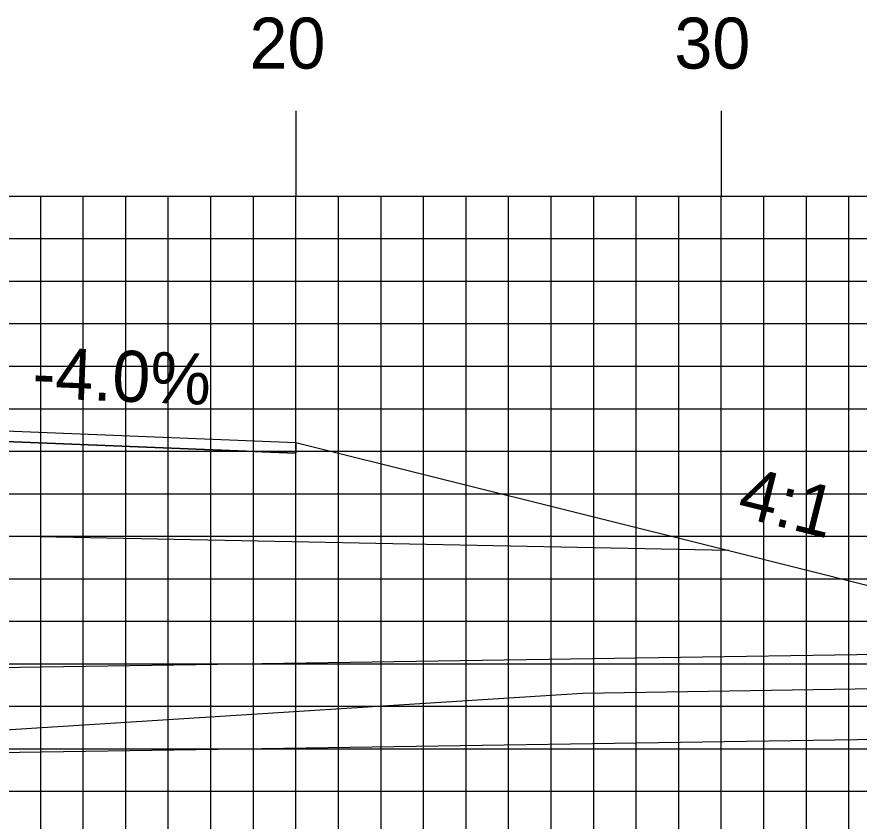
# Model space of a CAD drawing. Extents: x 1777531 to 1777875, y 442591 to 442811.
# Drawn here: x 1777710.72 to 1777730.52, y 442618.96 to 442637.88 of the extents above; entities that cross this region are included whole.
import ezdxf

# ---------------------------------------------------------------- set-up
doc = ezdxf.new("R2010")
doc.units = 0
for name, color, linetype in [('ANNOTATION', 7, 'Continuous'), ('D_Drainage_Culvert', 7, 'Continuous'), ('D_Roadway_Edge_Shoulder', 7, 'Continuous'), ('D_Roadway_SlopeLines', 7, 'Continuous'), ('D_Roadway_SubGrade', 7, 'Continuous'), ('H_V ANNOTATION', 7, 'Continuous'), ('MAJOR', 7, 'Continuous'), ('MINOR', 7, 'Continuous'), ('S_Roadway_Centerline', 7, 'Continuous')]:
    doc.layers.add(name, color=color, linetype=linetype)

msp = doc.modelspace()

# ---------------------------------------------------------------- linework, layer by layer
at = {"layer": 'D_Drainage_Culvert'}
for p, q in [((1777649.74, 442621.669), (1777737.74, 442622.989)), ((1777649.77, 442619.669), (1777737.77, 442620.989))]:
    msp.add_line(p, q, dxfattribs=at)
at = {"layer": 'D_Roadway_Edge_Shoulder'}
msp.add_lwpolyline([(1777709.277, 442628.189), (1777717.277, 442627.869), (1777717.277, 442627.619), (1777709.277, 442627.939)], close=True, dxfattribs=at)
at = {"layer": 'D_Roadway_SlopeLines'}
msp.add_lwpolyline([(1777717.277, 442627.869), (1777727.451, 442625.326), (1777730.758, 442624.499)], dxfattribs=at)
at = {"layer": 'D_Roadway_SubGrade'}
msp.add_lwpolyline([(1777685.277, 442625.689), (1777664.049, 442625.265), (1777673.932, 442627.736), (1777673.932, 442627.486), (1777685.277, 442627.939), (1777697.277, 442628.179), (1777709.277, 442627.939), (1777717.277, 442627.619), (1777717.277, 442627.869), (1777727.451, 442625.326), (1777709.277, 442625.689), (1777697.277, 442625.929)], close=True, dxfattribs=at)
at = {"layer": 'MAJOR'}
for p, q in [((1777717.277, 442635.669), (1777717.277, 442633.665)), ((1777727.277, 442635.669), (1777727.277, 442633.665)), ((1777557.277, 442633.665), (1777837.277, 442633.665)), ((1777557.277, 442633.665), (1777837.277, 442633.665)), ((1777717.277, 442608.665), (1777717.277, 442633.665)), ((1777727.277, 442608.665), (1777727.277, 442633.665)), ((1777557.277, 442628.665), (1777837.277, 442628.665)), ((1777557.277, 442623.665), (1777837.277, 442623.665))]:
    msp.add_line(p, q, dxfattribs=at)
at = {"layer": 'MINOR'}
for p, q in [((1777711.277, 442608.665), (1777711.277, 442633.665)), ((1777712.277, 442608.665), (1777712.277, 442633.665)), ((1777713.277, 442608.665), (1777713.277, 442633.665)), ((1777714.277, 442608.665), (1777714.277, 442633.665)), ((1777715.277, 442608.665), (1777715.277, 442633.665)), ((1777716.277, 442608.665), (1777716.277, 442633.665)), ((1777718.277, 442608.665), (1777718.277, 442633.665)), ((1777719.277, 442608.665), (1777719.277, 442633.665)), ((1777720.277, 442608.665), (1777720.277, 442633.665)), ((1777721.277, 442608.665), (1777721.277, 442633.665)), ((1777722.277, 442608.665), (1777722.277, 442633.665)), ((1777723.277, 442608.665), (1777723.277, 442633.665)), ((1777724.277, 442608.665), (1777724.277, 442633.665)), ((1777725.277, 442608.665), (1777725.277, 442633.665)), ((1777726.277, 442608.665), (1777726.277, 442633.665)), ((1777728.277, 442608.665), (1777728.277, 442633.665)), ((1777729.277, 442608.665), (1777729.277, 442633.665)), ((1777730.277, 442608.665), (1777730.277, 442633.665)), ((1777557.277, 442632.665), (1777837.277, 442632.665)), ((1777557.277, 442631.665), (1777837.277, 442631.665)), ((1777557.277, 442630.665), (1777837.277, 442630.665)), ((1777557.277, 442629.665), (1777837.277, 442629.665)), ((1777557.277, 442627.665), (1777837.277, 442627.665)), ((1777557.277, 442626.665), (1777837.277, 442626.665)), ((1777557.277, 442625.665), (1777837.277, 442625.665)), ((1777557.277, 442624.665), (1777837.277, 442624.665)), ((1777557.277, 442622.665), (1777837.277, 442622.665)), ((1777557.277, 442621.665), (1777837.277, 442621.665)), ((1777557.277, 442620.665), (1777837.277, 442620.665)), ((1777557.277, 442619.665), (1777837.277, 442619.665))]:
    msp.add_line(p, q, dxfattribs=at)
at = {"layer": 'S_Roadway_Centerline'}
msp.add_lwpolyline([(1777633.64, 442619.257), (1777646.456, 442619.566), (1777655.751, 442619.741), (1777669.078, 442620.093), (1777673.828, 442620.29), (1777677.649, 442620.237), (1777685.596, 442620.01), (1777693.64, 442620.461), (1777697.922, 442620.667), (1777701.791, 442620.763), (1777709.331, 442621.037), (1777724.017, 442621.975), (1777731.905, 442622.099), (1777741.337, 442622.578), (1777744.76, 442622.674), (1777747.718, 442622.714), (1777756.235, 442622.757)], dxfattribs=at)

# ---------------------------------------------------------------- texts
at = {"layer": 'ANNOTATION'}
for s, rotation, p in [('-4.0%', 357.7094, (1777711.069, 442628.919)), ('4:1', 345.9638, (1777727.61, 442626.148))]:
    msp.add_text(s, height=1.2, rotation=rotation, dxfattribs=at).set_placement(p)
at = {"layer": 'H_V ANNOTATION'}
for s, p in [('20', (1777716.185, 442636.665)), ('30', (1777726.174, 442636.665))]:
    msp.add_text(s, height=1.2, dxfattribs=at).set_placement(p)

doc.saveas('drawing.dxf')
